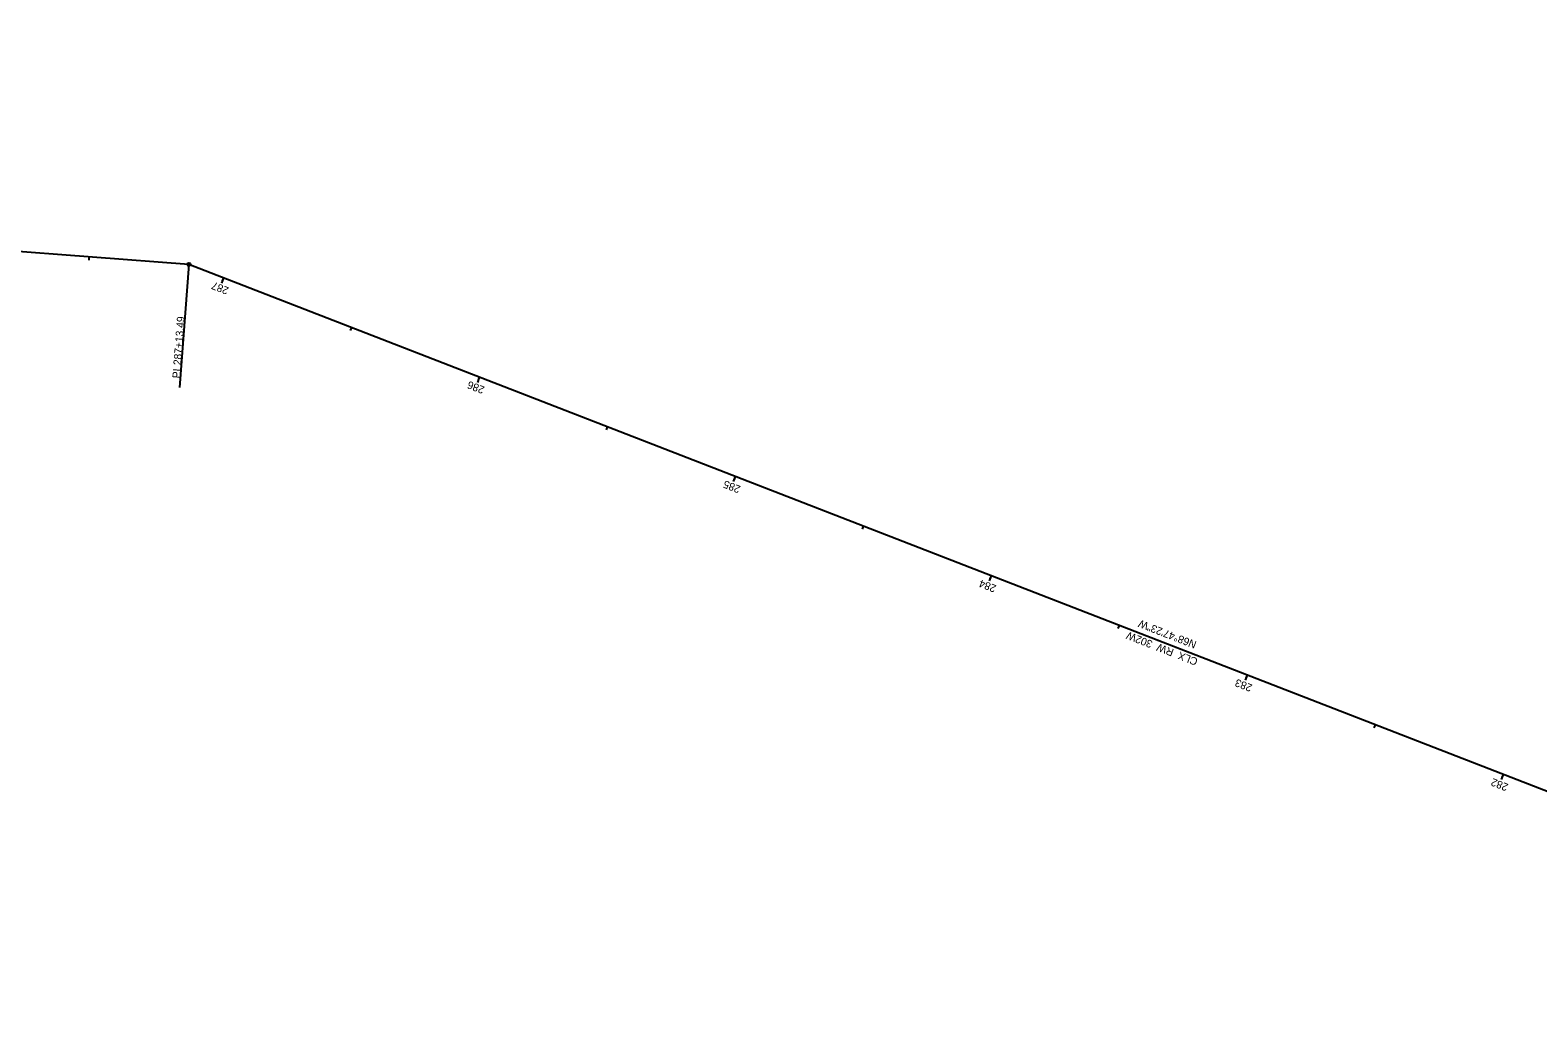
# Model space of a CAD drawing. Extents: x 2045805 to 2050091, y 455249 to 458900.
# Drawn here: x 2046864 to 2047414, y 456993 to 457354 of the extents above; entities that cross this region are included whole.
import ezdxf

# ---------------------------------------------------------------- set-up
doc = ezdxf.new("R2010")
doc.units = 0
for name, color, linetype in [('GE_P_Alignment_100_Bearings', 7, 'Continuous'), ('GE_P_Alignment_100_Cardinal_Points', 7, 'Continuous'), ('GE_P_Alignment_100_Curve_Data', 7, 'Continuous'), ('GE_P_Alignment_100_Distances', 7, 'Continuous'), ('GE_P_Alignment_100_Stations', 7, 'Continuous'), ('GE_P_Driveway_CL', 7, 'Continuous'), ('PF_P_Grade_Line', 7, 'Continuous'), ('PF_X_Ground_Line', 7, 'Continuous'), ('PV_P_EOP', 7, 'Continuous'), ('PV_X_EOP', 7, 'Continuous'), ('RW_X_CL_100_Stations', 7, 'Continuous'), ('SC_Scratch1', 7, 'Continuous'), ('SC_Scratch3', 7, 'Continuous')]:
    doc.layers.add(name, color=color, linetype=linetype)

msp = doc.modelspace()

# ---------------------------------------------------------------- linework, layer by layer
at = {"layer": 'GE_P_Alignment_100_Bearings'}
msp.add_line((2046922.17, 457268.65), (2046918.72, 457223.78), dxfattribs=at)
msp.add_circle((2046922.17, 457268.65), 0.6, dxfattribs=at)
at = {"layer": 'GE_P_Alignment_100_Cardinal_Points'}
for p, q in [((2046885.77, 457271.45), (2046885.68, 457270.25)), ((2046934.75, 457263.77), (2046934.02, 457261.9)), ((2046981.36, 457245.68), (2046980.93, 457244.56)), ((2047027.97, 457227.59), (2047027.25, 457225.72)), ((2047074.59, 457209.5), (2047074.15, 457208.38)), ((2047121.2, 457191.41), (2047120.48, 457189.55)), ((2047167.81, 457173.32), (2047167.38, 457172.2)), ((2047214.43, 457155.23), (2047213.7, 457153.37)), ((2047261.04, 457137.14), (2047260.6, 457136.02)), ((2047307.65, 457119.05), (2047306.93, 457117.19)), ((2047354.26, 457100.96), (2047353.83, 457099.84)), ((2047400.88, 457082.87), (2047400.15, 457081.01))]:
    msp.add_line(p, q, dxfattribs=at)
at = {"layer": 'GE_P_Alignment_100_Distances'}
msp.add_line((2046922.17, 457268.65), (2046918.72, 457223.78), dxfattribs=at)
msp.add_circle((2046922.17, 457268.65), 0.6, dxfattribs=at)
at = {"layer": 'GE_P_Alignment_100_Stations'}
for p, q in [((2046934.75, 457263.77), (2046934.31, 457262.65)), ((2047027.97, 457227.59), (2047027.54, 457226.47)), ((2047121.2, 457191.41), (2047120.48, 457189.55)), ((2047214.43, 457155.23), (2047213.99, 457154.11)), ((2047307.65, 457119.05), (2047307.22, 457117.93)), ((2047400.88, 457082.87), (2047400.44, 457081.75))]:
    msp.add_line(p, q, dxfattribs=at)
at = {"layer": 'PF_P_Grade_Line'}
msp.add_line((2046922.17, 457268.65), (2046918.72, 457223.78), dxfattribs=at)
msp.add_circle((2046922.17, 457268.65), 0.6, dxfattribs=at)
at = {"layer": 'PV_P_EOP'}
for p, q in [((2046922.17, 457268.65), (2045811.12, 457354.01)), ((2047631.2, 456993.49), (2046922.17, 457268.65))]:
    msp.add_line(p, q, dxfattribs=at)
at = {"layer": 'PV_X_EOP'}
msp.add_line((2047121.2, 457191.41), (2047120.77, 457190.29), dxfattribs=at)

# ---------------------------------------------------------------- texts
at = {"layer": 'GE_P_Alignment_100_Bearings'}
for s, p in [('287+13.49', (2046919.3, 457231.87)), ('PI', (2046918.93, 457227.1))]:
    msp.add_text(s, height=2.8, rotation=85.6064, dxfattribs=at).set_placement(p)
at = {"layer": 'GE_P_Alignment_100_Cardinal_Points'}
for s, p in [('287', (2046936.94, 457260.19)), ('286', (2047030.11, 457224.03)), ('285', (2047123.35, 457187.84)), ('284', (2047216.52, 457151.68)), ('283', (2047309.77, 457115.5)), ('282', (2047403.01, 457079.31))]:
    msp.add_text(s, height=2.8, rotation=158.7898, dxfattribs=at).set_placement(p)
at = {"layer": 'GE_P_Alignment_100_Curve_Data'}
msp.add_text('N68°47\'23"W', height=2.8, rotation=158.7898, dxfattribs=at).set_placement((2047289.49, 457131.25))
at = {"layer": 'GE_P_Alignment_100_Distances'}
for s, p in [('287+13.49', (2046919.3, 457231.87)), ('PI', (2046918.93, 457227.1))]:
    msp.add_text(s, height=2.8, rotation=85.6064, dxfattribs=at).set_placement(p)
at = {"layer": 'GE_P_Alignment_100_Stations'}
msp.add_text('285', height=2.8, rotation=158.7898, dxfattribs=at).set_placement((2047123.35, 457187.84))
at = {"layer": 'GE_P_Driveway_CL'}
msp.add_text('CLX_RW_302W', height=2.8, rotation=158.7898, dxfattribs=at).set_placement((2047289.95, 457125.04))
at = {"layer": 'PF_P_Grade_Line'}
for s, p in [('287+13.49', (2046919.3, 457231.87)), ('PI', (2046918.93, 457227.1))]:
    msp.add_text(s, height=2.8, rotation=85.6064, dxfattribs=at).set_placement(p)
at = {"layer": 'PF_X_Ground_Line'}
msp.add_text('N68°47\'23"W', height=2.8, rotation=158.7898, dxfattribs=at).set_placement((2047289.49, 457131.25))
at = {"layer": 'RW_X_CL_100_Stations'}
msp.add_text('CLX_RW_302W', height=2.8, rotation=158.7898, dxfattribs=at).set_placement((2047289.95, 457125.04))
at = {"layer": 'SC_Scratch1'}
msp.add_text('N68°47\'23"W', height=2.8, rotation=158.7898, dxfattribs=at).set_placement((2047289.49, 457131.25))
at = {"layer": 'SC_Scratch3'}
msp.add_text('CLX_RW_302W', height=2.8, rotation=158.7898, dxfattribs=at).set_placement((2047289.95, 457125.04))

doc.saveas('drawing.dxf')
